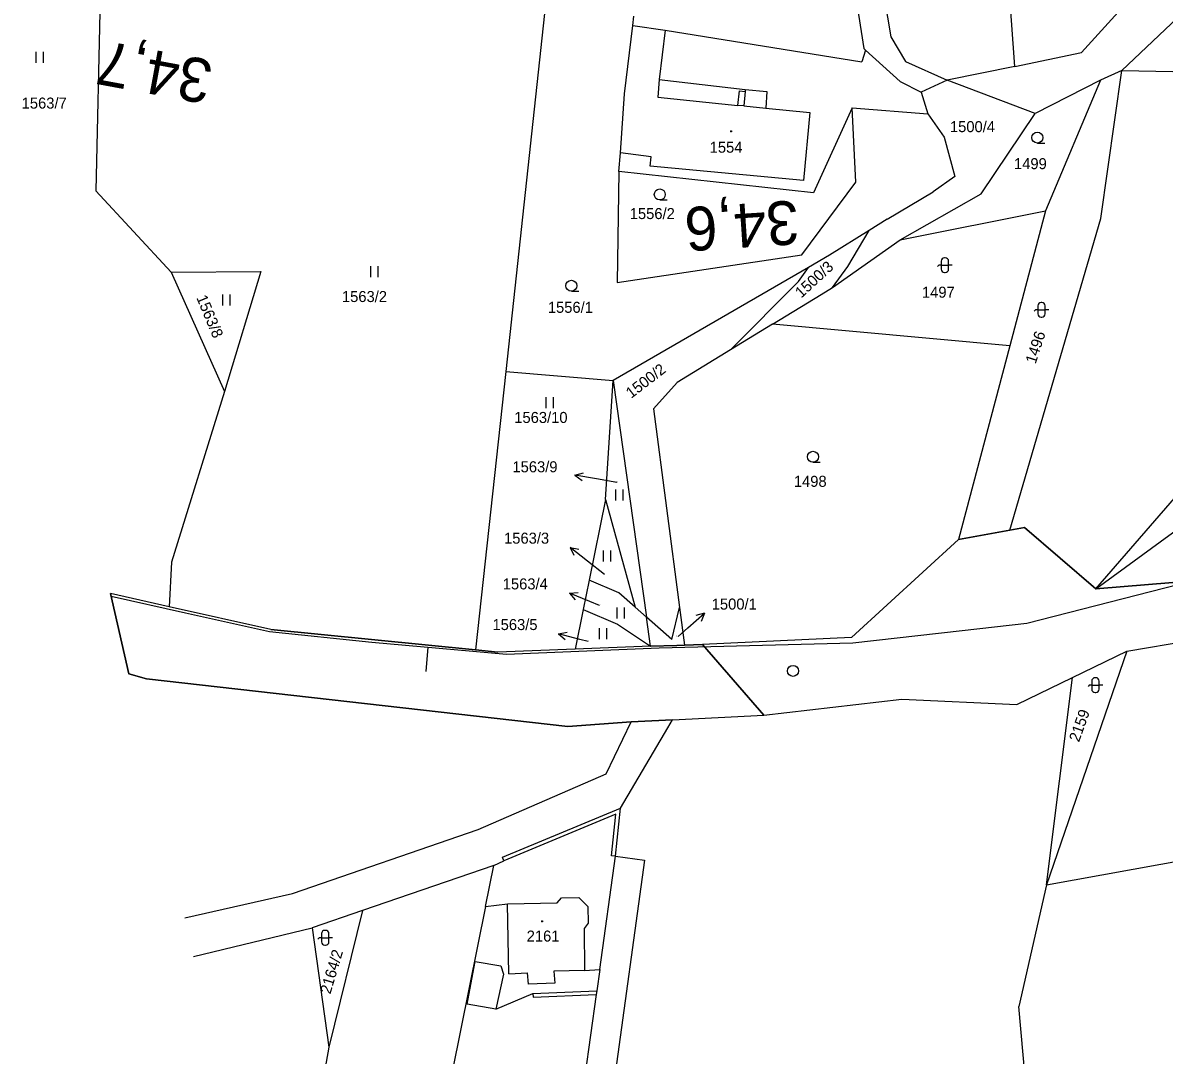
# Model space of a CAD drawing. Extents: x -805730 to -804640, y -1150889 to -1150366.
# Drawn here: x -805508.9 to -805353.5, y -1150740.9 to -1150600.3 of the extents above; entities that cross this region are included whole.
import ezdxf

# ---------------------------------------------------------------- set-up
doc = ezdxf.new("R2010")
doc.units = 0
for name, color, linetype in [('Default', 7, 'Continuous'), ('kilometráž - vrstava 7', 7, 'Continuous'), ('kn_celek - Cisla parcel pomocna', 7, 'Continuous'), ('kn_celek - Cisla pozemkovych parcel', 7, 'Continuous'), ('kn_celek - Cisla stavebnich parcel', 7, 'Continuous'), ('kn_celek - Hranice parcel', 7, 'Continuous'), ('kn_celek - Vnitrni kresby', 7, 'Continuous'), ('kn_celek - Znacky budov', 7, 'Continuous'), ('kn_celek - Znacky kultur', 7, 'Continuous'), ('plochy - SZDC', 7, 'Continuous'), ('PSR_C2_2_trasa_Vimperk - Kabelová trasa', 7, 'Continuous')]:
    doc.layers.add(name, color=color, linetype=linetype)

# ---------------------------------------------------------------- blocks, each defined once
blk = doc.blocks.new('316')
at = {"layer": 'Default'}
for p, q in [((0.5, 20), (-0.5, 20)), ((-8.3, 10), (-10, 8.1)), ((-5, 10), (-8.3, 10)), ((-5, 15.5), (-5, 4.5)), ((-5, 10), (5, 10)), ((-0.5, 0), (0.5, 0)), ((5, 4.5), (5, 15.5)), ((10, 10), (5, 10))]:
    blk.add_line(p, q, dxfattribs=at)
for centre, start, end in [((-0.5, 15.5), 90, 180), ((0.5, 15.5), 0, 90), ((-0.5, 4.5), 180, 270), ((0.5, 4.5), 270, 0)]:
    blk.add_arc(centre, 4.5, start, end, dxfattribs=at)
blk = doc.blocks.new('304')
at = {"layer": 'Default'}
blk.add_line((-0.1, 0), (9.9, 0), dxfattribs=at)
blk.add_circle((-0.1, 7.5), 7.5, dxfattribs=at)
blk = doc.blocks.new('306')
at = {"layer": 'Default'}
for p, q in [((-5.2, 0), (-5.2, 15)), ((4.8, 0), (4.8, 15))]:
    blk.add_line(p, q, dxfattribs=at)
blk = doc.blocks.new('402')
at = {"layer": 'Default'}
for p, q in [((-0.8, 0.8), (0.7, 0.8)), ((-0.8, 0.8), (-0.8, -0.7)), ((0.7, 0.8), (0.7, -0.7)), ((0.7, -0.7), (-0.8, -0.7))]:
    blk.add_line(p, q, dxfattribs=at)
blk = doc.blocks.new('Z61')
at = {"layer": 'Default'}
for p, q in [((0, 0), (30, 0)), ((30, 0), (19.2, 5.3)), ((30, 0), (19.2, -5.3))]:
    blk.add_line(p, q, dxfattribs=at)

msp = doc.modelspace()

# ---------------------------------------------------------------- linework, layer by layer
at = {"layer": 'kilometráž - vrstava 7'}
msp.add_circle((-805404.03, -1150688.55), 0.75, dxfattribs=at)
at = {"layer": 'kn_celek - Cisla parcel pomocna'}
for p, q in [((-805428, -1150662.88), (-805430.77, -1150662.41)), ((-805429.72, -1150675.42), (-805432.02, -1150673.59)), ((-805430.36, -1150679.64), (-805431.7, -1150679.09)), ((-805419.69, -1150683.87), (-805418.35, -1150682.69)), ((-805431.94, -1150684.55), (-805433.05, -1150684.26))]:
    msp.add_line(p, q, dxfattribs=at)
at = {"layer": 'kn_celek - Hranice parcel'}
for p, q in [((-805395.01, -1150576.39), (-805390.72, -1150602.19)), ((-805373.83, -1150606.21), (-805375.32, -1150585.4)), ((-805396.94, -1150587.46), (-805394.39, -1150603.79)), ((-805498.17, -1150587.83), (-805498.93, -1150623.15)), ((-805343.57, -1150591.91), (-805359.29, -1150606.79)), ((-805354.86, -1150593.35), (-805364.74, -1150604.34)), ((-805437.68, -1150597.31), (-805443.12, -1150647.75)), ((-805425.86, -1150600.64), (-805425.71, -1150599.38)), ((-805426.96, -1150609.96), (-805425.86, -1150600.64)), ((-805425.86, -1150600.64), (-805421.43, -1150601.26)), ((-805421.43, -1150601.26), (-805394.68, -1150605.57)), ((-805390.72, -1150602.19), (-805388.71, -1150605.55)), ((-805394.15, -1150604), (-805394.68, -1150605.57)), ((-805394.15, -1150604), (-805394.39, -1150603.79)), ((-805394.15, -1150604), (-805389.43, -1150608.29)), ((-805373.83, -1150606.21), (-805364.74, -1150604.34)), ((-805388.71, -1150605.55), (-805383.03, -1150608.11)), ((-805373.83, -1150606.21), (-805383.03, -1150608.11)), ((-805359.29, -1150606.79), (-805362.16, -1150608.08)), ((-805362.11, -1150626.95), (-805359.29, -1150606.79)), ((-805359.29, -1150606.79), (-805347.74, -1150606.97)), ((-805389.43, -1150608.29), (-805386.57, -1150609.73)), ((-805383.03, -1150608.11), (-805386.57, -1150609.73)), ((-805371.06, -1150612.65), (-805383.03, -1150608.11)), ((-805362.16, -1150608.08), (-805371.06, -1150612.65)), ((-805362.16, -1150608.08), (-805369.64, -1150625.9)), ((-805427.52, -1150617.99), (-805426.96, -1150609.96)), ((-805386.57, -1150609.73), (-805385.69, -1150612.69)), ((-805395.97, -1150611.87), (-805401.26, -1150623.42)), ((-805395.49, -1150621.99), (-805395.97, -1150611.87)), ((-805395.97, -1150611.87), (-805385.69, -1150612.69)), ((-805385.69, -1150612.69), (-805383.44, -1150615.84)), ((-805378.44, -1150623.56), (-805371.06, -1150612.65)), ((-805383.44, -1150615.84), (-805382.01, -1150621.22)), ((-805427.76, -1150620.52), (-805427.52, -1150617.99)), ((-805427.76, -1150620.52), (-805427.97, -1150635.67)), ((-805401.26, -1150623.42), (-805427.76, -1150620.52)), ((-805382.01, -1150621.22), (-805384.97, -1150623.32)), ((-805498.93, -1150623.15), (-805488.68, -1150634.22)), ((-805402.84, -1150631.87), (-805395.49, -1150621.99)), ((-805391.22, -1150627.03), (-805384.97, -1150623.32)), ((-805389.47, -1150629.85), (-805378.44, -1150623.56)), ((-805389.47, -1150629.85), (-805369.64, -1150625.9)), ((-805369.64, -1150625.9), (-805374.51, -1150644.26)), ((-805391.22, -1150627.03), (-805393.65, -1150628.55)), ((-805374.52, -1150669.39), (-805362.11, -1150626.95)), ((-805393.65, -1150628.55), (-805399.05, -1150631.93)), ((-805396.57, -1150633.45), (-805393.65, -1150628.55)), ((-805398.64, -1150636.34), (-805389.47, -1150629.85)), ((-805427.97, -1150635.67), (-805402.84, -1150631.87)), ((-805399.05, -1150631.93), (-805401.93, -1150633.6)), ((-805488.68, -1150634.22), (-805476.47, -1150634.17)), ((-805488.68, -1150634.22), (-805481.42, -1150650.51)), ((-805476.47, -1150634.17), (-805481.42, -1150650.51)), ((-805401.93, -1150633.6), (-805428.5, -1150648.99)), ((-805403.27, -1150635.51), (-805401.93, -1150633.6)), ((-805398.64, -1150636.34), (-805396.57, -1150633.45)), ((-805412.53, -1150644.8), (-805403.27, -1150635.51)), ((-805406.84, -1150641.34), (-805400.21, -1150637.3)), ((-805400.21, -1150637.3), (-805398.64, -1150636.34)), ((-805362.8, -1150677.38), (-805327.08, -1150636.08)), ((-805406.84, -1150641.34), (-805412.53, -1150644.8)), ((-805374.51, -1150644.26), (-805406.84, -1150641.34)), ((-805412.56, -1150644.82), (-805419.82, -1150649.25)), ((-805412.53, -1150644.8), (-805412.56, -1150644.82)), ((-805374.51, -1150644.26), (-805381.52, -1150670.67)), ((-805443.12, -1150647.75), (-805447.24, -1150685.68)), ((-805443.12, -1150647.75), (-805428.5, -1150648.99)), ((-805429.56, -1150665.22), (-805428.5, -1150648.99)), ((-805428.5, -1150648.99), (-805423.98, -1150681.23)), ((-805423.01, -1150652.86), (-805419.82, -1150649.25)), ((-805481.42, -1150650.51), (-805488.65, -1150673.73)), ((-805423.01, -1150652.86), (-805419.48, -1150679.92)), ((-805429.56, -1150665.22), (-805431.79, -1150676.21)), ((-805429.56, -1150665.22), (-805425.54, -1150679.86)), ((-805362.8, -1150677.38), (-805347.06, -1150665.86)), ((-805381.52, -1150670.67), (-805374.52, -1150669.39)), ((-805374.52, -1150669.39), (-805372.51, -1150669.03)), ((-805372.51, -1150669.03), (-805362.8, -1150677.38)), ((-805396.07, -1150684.02), (-805381.52, -1150670.67)), ((-805488.65, -1150673.73), (-805488.96, -1150679.81)), ((-805431.79, -1150676.21), (-805432.6, -1150680.19)), ((-805427.75, -1150677.92), (-805431.79, -1150676.21)), ((-805362.8, -1150677.38), (-805352.32, -1150676.52)), ((-805358.57, -1150685.85), (-805308.19, -1150677.39)), ((-805488.96, -1150679.81), (-805496.95, -1150678.01)), ((-805425.54, -1150679.86), (-805427.75, -1150677.92)), ((-805475.13, -1150682.93), (-805488.96, -1150679.81)), ((-805432.6, -1150680.19), (-805433.7, -1150685.59)), ((-805432.6, -1150680.19), (-805427.91, -1150682.2)), ((-805423.98, -1150681.23), (-805425.54, -1150679.86)), ((-805420.52, -1150684.26), (-805419.48, -1150679.92)), ((-805419.48, -1150679.92), (-805418.81, -1150685.03)), ((-805427.91, -1150682.2), (-805423.42, -1150685.2)), ((-805423.42, -1150685.2), (-805423.98, -1150681.23)), ((-805420.52, -1150684.26), (-805423.98, -1150681.23)), ((-805475.13, -1150682.93), (-805447.24, -1150685.68)), ((-805423.42, -1150685.2), (-805433.7, -1150685.59)), ((-805423.42, -1150685.2), (-805419.87, -1150685.07)), ((-805419.87, -1150685.07), (-805418.81, -1150685.03)), ((-805418.81, -1150685.03), (-805416.34, -1150684.94)), ((-805396.07, -1150684.02), (-805416.34, -1150684.94)), ((-805416.34, -1150684.94), (-805408.01, -1150694.56)), ((-805447.24, -1150685.68), (-805444.22, -1150685.98)), ((-805433.7, -1150685.59), (-805444.22, -1150685.98)), ((-805358.57, -1150685.85), (-805369.54, -1150717.67)), ((-805365.99, -1150689.46), (-805358.57, -1150685.85)), ((-805492.06, -1150689.65), (-805494.44, -1150688.97)), ((-805434.71, -1150696.14), (-805492.06, -1150689.65)), ((-805373.55, -1150693.14), (-805365.99, -1150689.46)), ((-805369.54, -1150717.67), (-805365.99, -1150689.46)), ((-805408.01, -1150694.56), (-805389.21, -1150692.42)), ((-805389.21, -1150692.42), (-805373.55, -1150693.14)), ((-805420.42, -1150695.2), (-805408.01, -1150694.56)), ((-805426.08, -1150695.49), (-805434.71, -1150696.14)), ((-805429.45, -1150702.56), (-805426.08, -1150695.49)), ((-805427.5, -1150707.23), (-805421.06, -1150696.29)), ((-805420.42, -1150695.2), (-805426.08, -1150695.49)), ((-805421.06, -1150696.29), (-805420.42, -1150695.2)), ((-805446.9, -1150710.15), (-805429.45, -1150702.56)), ((-805443.58, -1150713.94), (-805427.5, -1150707.23)), ((-805428.21, -1150713.8), (-805427.5, -1150707.23)), ((-805472.19, -1150718.89), (-805446.9, -1150710.15)), ((-805444.78, -1150715.07), (-805443.38, -1150714.43)), ((-805443.38, -1150714.43), (-805443.58, -1150713.94)), ((-805424.25, -1150714.35), (-805436.99, -1150806.72)), ((-805430.35, -1150729.23), (-805428.21, -1150713.8)), ((-805428.21, -1150713.8), (-805424.25, -1150714.35)), ((-805369.54, -1150717.67), (-805350.19, -1150714.2)), ((-805444.78, -1150715.07), (-805462.65, -1150721.2)), ((-805445.91, -1150720.66), (-805444.78, -1150715.07)), ((-805369.54, -1150717.67), (-805373.3, -1150734.28)), ((-805486.85, -1150722.18), (-805472.19, -1150718.89)), ((-805462.65, -1150721.2), (-805469.5, -1150723.55)), ((-805462.65, -1150721.2), (-805467.24, -1150739.8)), ((-805445.91, -1150720.66), (-805450.4, -1150742.95)), ((-805485.65, -1150727.43), (-805469.5, -1150723.55)), ((-805469.5, -1150723.55), (-805467.24, -1150739.8)), ((-805430.35, -1150729.23), (-805430.75, -1150732.12)), ((-805430.75, -1150732.12), (-805430.82, -1150732.62)), ((-805430.82, -1150732.62), (-805432.36, -1150743.71)), ((-805371.44, -1150755.25), (-805373.3, -1150734.28)), ((-805467.24, -1150739.8), (-805471.05, -1150761.74))]:
    msp.add_line(p, q, dxfattribs=at)
at = {"layer": 'kn_celek - Vnitrni kresby'}
for p, q in [((-805421.43, -1150601.26), (-805422.26, -1150608)), ((-805422.26, -1150608), (-805422.43, -1150610.42)), ((-805422.26, -1150608), (-805410.54, -1150609.36)), ((-805410.54, -1150609.36), (-805410.55, -1150609.61)), ((-805410.54, -1150609.36), (-805407.6, -1150609.64)), ((-805422.43, -1150610.42), (-805411.55, -1150611.52)), ((-805411.55, -1150611.52), (-805411.34, -1150609.53)), ((-805411.34, -1150609.53), (-805410.55, -1150609.61)), ((-805410.55, -1150609.61), (-805410.75, -1150611.6)), ((-805407.6, -1150609.64), (-805407.73, -1150611.91)), ((-805410.75, -1150611.6), (-805411.55, -1150611.52)), ((-805410.75, -1150611.6), (-805407.73, -1150611.91)), ((-805407.73, -1150611.91), (-805401.76, -1150612.51)), ((-805401.76, -1150612.51), (-805402.59, -1150621.76)), ((-805423.33, -1150618.54), (-805427.52, -1150617.99)), ((-805423.49, -1150619.78), (-805423.33, -1150618.54)), ((-805402.59, -1150621.76), (-805423.49, -1150619.78)), ((-805428.14, -1150708.07), (-805443.38, -1150714.43)), ((-805428.75, -1150713.74), (-805428.14, -1150708.07)), ((-805428.21, -1150713.8), (-805428.75, -1150713.74)), ((-805436.12, -1150720.13), (-805435.57, -1150719.46)), ((-805435.57, -1150719.46), (-805433.17, -1150719.41)), ((-805433.17, -1150719.41), (-805431.97, -1150720.62)), ((-805445.91, -1150720.66), (-805442.92, -1150720.3)), ((-805442.92, -1150720.3), (-805436.12, -1150720.13)), ((-805442.7, -1150729.8), (-805442.92, -1150720.3)), ((-805431.97, -1150720.62), (-805431.92, -1150722.89)), ((-805431.92, -1150722.89), (-805432.48, -1150723.62)), ((-805432.48, -1150723.62), (-805432.4, -1150729.34)), ((-805448.38, -1150733.93), (-805447.3, -1150728.15)), ((-805447.3, -1150728.15), (-805443.8, -1150728.74)), ((-805443.8, -1150728.74), (-805443.46, -1150729.86)), ((-805443.46, -1150729.86), (-805444.47, -1150734.61)), ((-805442.7, -1150729.8), (-805440.16, -1150729.69)), ((-805440.06, -1150731.21), (-805440.16, -1150729.69)), ((-805432.4, -1150729.34), (-805436.59, -1150729.47)), ((-805436.59, -1150729.47), (-805436.48, -1150731.08)), ((-805432.4, -1150729.34), (-805430.35, -1150729.23)), ((-805436.48, -1150731.08), (-805440.06, -1150731.21)), ((-805439.45, -1150732.48), (-805430.75, -1150732.12)), ((-805444.47, -1150734.61), (-805439.45, -1150732.48)), ((-805439.45, -1150732.48), (-805439.43, -1150732.98)), ((-805439.43, -1150732.98), (-805430.82, -1150732.62)), ((-805444.47, -1150734.61), (-805448.38, -1150733.93))]:
    msp.add_line(p, q, dxfattribs=at)
at = {"layer": 'plochy - SZDC'}
for p, q in [((-805374.52, -1150669.39), (-805381.52, -1150670.67)), ((-805372.51, -1150669.03), (-805374.52, -1150669.39)), ((-805362.8, -1150677.38), (-805372.51, -1150669.03)), ((-805381.52, -1150670.67), (-805396.07, -1150684.02)), ((-805352.32, -1150676.52), (-805362.8, -1150677.38)), ((-805358.57, -1150685.85), (-805308.19, -1150677.39)), ((-805494.44, -1150688.97), (-805496.95, -1150678.01)), ((-805488.96, -1150679.81), (-805496.95, -1150678.01)), ((-805496.95, -1150678.01), (-805494.44, -1150688.97)), ((-805475.13, -1150682.93), (-805488.96, -1150679.81)), ((-805447.24, -1150685.68), (-805475.13, -1150682.93)), ((-805423.42, -1150685.2), (-805433.7, -1150685.59)), ((-805419.87, -1150685.07), (-805423.42, -1150685.2)), ((-805418.81, -1150685.03), (-805419.87, -1150685.07)), ((-805416.34, -1150684.94), (-805418.81, -1150685.03)), ((-805396.07, -1150684.02), (-805416.34, -1150684.94)), ((-805416.34, -1150684.94), (-805408.01, -1150694.56)), ((-805408.01, -1150694.56), (-805416.34, -1150684.94)), ((-805444.22, -1150685.98), (-805447.24, -1150685.68)), ((-805433.7, -1150685.59), (-805444.22, -1150685.98)), ((-805365.99, -1150689.46), (-805358.57, -1150685.85)), ((-805494.44, -1150688.97), (-805492.06, -1150689.65)), ((-805492.06, -1150689.65), (-805434.71, -1150696.14)), ((-805373.55, -1150693.14), (-805365.99, -1150689.46)), ((-805408.01, -1150694.56), (-805389.21, -1150692.42)), ((-805389.21, -1150692.42), (-805373.55, -1150693.14)), ((-805420.42, -1150695.2), (-805408.01, -1150694.56)), ((-805434.71, -1150696.14), (-805426.08, -1150695.49)), ((-805426.08, -1150695.49), (-805420.42, -1150695.2))]:
    msp.add_line(p, q, dxfattribs=at)
at = {"layer": 'PSR_C2_2_trasa_Vimperk - Kabelová trasa'}
msp.add_line((-805453.99, -1150688.64), (-805453.72, -1150685.33), dxfattribs=at)
for points in [[(-805372.22, -1150682.03), (-805349.68, -1150676.27), (-805317.98, -1150667.75), (-805311.89, -1150666.33), (-805283.81, -1150660.76), (-805266.17, -1150658.11), (-805251.29, -1150654.49), (-805239.52, -1150653.99)], [(-805496.87, -1150678.36), (-805486.72, -1150680.63), (-805475.31, -1150683.18), (-805461.35, -1150684.65), (-805443.05, -1150686.29), (-805422.27, -1150685.42)], [(-805422.27, -1150685.42), (-805395.91, -1150684.71), (-805381.01, -1150683.04), (-805372.22, -1150682.03)]]:
    msp.add_lwpolyline(points, dxfattribs=at)

# ---------------------------------------------------------------- block references
at = {"layer": 'kn_celek - Cisla parcel pomocna'}
for p, xscale, yscale, rotation in [((-805430.77, -1150662.41), 0.1, 0.10000000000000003, 170.4366), ((-805432.02, -1150673.59), 0.09999999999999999, 0.10000000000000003, 141.49071000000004), ((-805431.7, -1150679.09), 0.09999999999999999, 0.10000000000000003, 157.69692), ((-805418.35, -1150682.69), 0.1, 0.10000000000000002, 41.444730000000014), ((-805433.05, -1150684.26), 0.09999999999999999, 0.10000000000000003, 165.19320000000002)]:
    msp.add_blockref('Z61', p, dxfattribs=dict(at, xscale=xscale, yscale=yscale, rotation=rotation))
at = {"layer": 'kn_celek - Znacky budov', "xscale": 0.1, "yscale": 0.10000000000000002}
for p in [(-805412.48, -1150615.07), (-805438.21, -1150722.66)]:
    msp.add_blockref('402', p, dxfattribs=at)
at = {"layer": 'kn_celek - Znacky kultur', "xscale": 0.1, "yscale": 0.10000000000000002}
for name, p in [('306', (-805506.57, -1150605.71)), ('304', (-805370.76, -1150616.66)), ('304', (-805422.16, -1150624.41)), ('316', (-805383.35, -1150634.28)), ('306', (-805460.99, -1150634.94)), ('304', (-805434.2, -1150636.84)), ('306', (-805481.14, -1150638.78)), ('316', (-805370.2, -1150640.38)), ('306', (-805437.1, -1150652.75)), ('304', (-805401.31, -1150660.14)), ('306', (-805427.64, -1150665.35)), ('306', (-805429.31, -1150673.67)), ('306', (-805427.46, -1150681.41)), ('306', (-805429.88, -1150684.22)), ('316', (-805362.87, -1150691.48)), ('316', (-805467.71, -1150725.89))]:
    msp.add_blockref(name, p, dxfattribs=at)

# ---------------------------------------------------------------- texts
at = {"layer": 'kilometráž - vrstava 7'}
for s, height, rotation, p in [('34,7', 6, 169.5145, (-805482.74, -1150605.49)), ('34,6', 5.969, 183.7495, (-805403.44, -1150624.44))]:
    msp.add_text(s, height=height, rotation=rotation, dxfattribs=at).set_placement(p)
at = {"layer": 'kn_celek - Cisla parcel pomocna'}
for s, p in [('1563/9', (-805442.23, -1150661.5)), ('1563/3', (-805443.37, -1150671.22)), ('1563/4', (-805443.55, -1150677.45)), ('1500/1', (-805415.1, -1150680.2)), ('1563/5', (-805444.95, -1150682.99))]:
    msp.add_text(s, height=1.5, dxfattribs=at).set_placement(p)
at = {"layer": 'kn_celek - Cisla pozemkovych parcel'}
for s, height, p in [('1563/7', 1.5, (-805509.04, -1150611.96)), ('1500/4', 1.5, (-805382.67, -1150615.17)), ('1499', 1.5, (-805373.95, -1150620.21)), ('1556/2', 1.5, (-805426.26, -1150627.01)), ('1563/2', 1.5, (-805465.44, -1150638.31)), ('1497', 1.5, (-805386.48, -1150637.72)), ('1556/1', 1.5, (-805437.41, -1150639.78)), ('1563/10', 1.5, (-805441.98, -1150654.78)), ('1498', 1.5, (-805403.92, -1150663.48)), ('1563/9', 0.1, (-805428.26, -1150662.85)), ('1563/3', 0.1, (-805429.99, -1150675.39)), ('1563/4', 0.1, (-805430.63, -1150679.61)), ('1500/1', 0.1, (-805419.94, -1150683.84)), ('1563/5', 0.1, (-805432.21, -1150684.52))]:
    msp.add_text(s, height=height, dxfattribs=at).set_placement(p)
for s, rotation, p in [('1500/3', 42.5522, (-805402.91, -1150637.84)), ('1563/8', 292.697, (-805485.29, -1150637.71)), ('1496', 72, (-805371.01, -1150646.82)), ('1500/2', 37.5789, (-805426.07, -1150651.5)), ('2159', 70.3481, (-805365.1, -1150698.33)), ('2164/2', 73.4473, (-805467.02, -1150732.66))]:
    msp.add_text(s, height=1.5, rotation=rotation, dxfattribs=at).set_placement(p)
at = {"layer": 'kn_celek - Cisla stavebnich parcel'}
for s, p in [('1554', (-805415.38, -1150617.97)), ('2161', (-805440.29, -1150725.42))]:
    msp.add_text(s, height=1.5, dxfattribs=at).set_placement(p)

doc.saveas('drawing.dxf')
